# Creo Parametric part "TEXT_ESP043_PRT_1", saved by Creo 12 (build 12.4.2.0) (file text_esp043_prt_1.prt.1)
Units: Custom; MM, KILOGRAM, SECS

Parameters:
  PTC_WM_ITERATION = "0"
  PTC_WM_VERSION = "-.0"
  PTC_WM_LIFECYCLE_STATE = "In Work"
  PTC_WM_LIFECYCLE = "MO_CADDocument"
  PTC_WM_CREATED_BY = "Maximilian Roepper (Z0017RMS: MO)"
  PTC_WM_CREATED_ON = "18-Sep-26 11:36:42 AM"
  PTC_WM_MODIFIED_BY = "Maximilian Roepper (Z0017RMS: MO)"
  PTC_WM_MODIFIED_ON = "18-Sep-26 11:36:46 AM"
  PDMLINKNUMBER = "PDM000071455239"
  PTC_WM_NAME = "text_esp043_prt_1.prt"
  PTC_WM_NUMBER = "PDM000071455239"

Other parameters: WEIGHT, WEIGHT_FACTOR, WEIGHT_ADD, _MASS_TEMP, _DIFF_TEMP, MC_ERRORS, SUPPLIER

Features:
  1. coordinate system
  2. datum plane "PRT_YZ"
  3. datum plane "PRT_XY"
  4. datum plane "PRT_XZ"
  5. coordinate system
  6. datum axis
  7. datum axis
  8. datum axis
  9. coordinate system
  10. imported feature
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
Other named items: PRT, SIEMENS_MO, DRW_VIEW_ORG, PRT_X, PRT_Y, PRT_Z, CS0, ROUGH_GROB

Layers: 00_STD_CSYS-KSYS, 01_STD_PLANES-EBENEN, 02_STD_AXES-ACHSEN, 03_STD_CSYS-KSYS, 24_IMPORT_FEAT-IMPORT_KE

Surfaces: 18 tabulated cylinder, 6 plane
